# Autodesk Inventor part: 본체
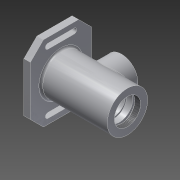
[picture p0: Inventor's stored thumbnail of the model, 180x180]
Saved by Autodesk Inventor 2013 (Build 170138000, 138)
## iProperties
Created: 2017-10
Part Number: 본체
Material: 알루미늄 6061
Document SubType Name: Modeling
Designer: Administrator
Density: 2.71 g/cm^3
Mass: 740.593 g
Surface Area: 658.234 cm^2
Volume: 273.281 cm^3
Author: Administrator
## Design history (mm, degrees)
sketch "스케치1"
  geometry: L1 (44.5, 35)-(57.5, 35); L2 (-57.5, 31)-(44.5, 31); L3 (44.5, 31)-(44.5, 35); L4 (57.5, 35)-(57.5, 0); L5 (57.5, 0)-(-57.5, 0); L6 (-57.5, 0)-(-57.5, 31); 2 further points
  constraints: 12 end point, 3 horizontal, 3 vertical, 2 coincident, 1 midpoint
  dimensions: "d0" = 35 distance from line of point (0, 0) L1; "d1" = 31 distance from line of point (0, 0) L2; "d2" = 115 distance between parallel lines of L6 L4; "d3" = 13 distance between parallel lines of L4 L3
revolve "회전1" sketch "스케치1" stored, may be unused: angle "d4" = 90 deg
sketch "스케치2"
  geometry: L1 (-58, 47)-(58, 47); L2 (58, 47)-(58, -47); L3 (58, -47)-(-58, -47); L4 (-58, -47)-(-58, 47); C1 r 35 at (0, 0) reference; 2 further points
  constraints: 8 end point, 2 midpoint, 2 parallel, 1 horizontal, 1 horizontal alignment, 1 perpendicular, 1 vertical alignment
  dimensions: "d5" = 116 distance of L2.end L3.end; "d7" = 94 distance of L1.end L2.end
extrude "돌출1" join sketch "스케치2" distance "d8" = 10; taper "d9" = 0 deg
chamfer "모따기1" distance "d10" = 20; stored, may be unused: second distance "d11" = 2, angle "d12" = 45 deg
sketch "스케치3"
  geometry: L1 (42, 24)-(50, 24); L2 (50, 24)-(50, -24); L3 (50, -24)-(42, -24); L4 (42, -24)-(42, 24); L5 (-50, -24)-(-42, -24); L6 (-42, -24)-(-42, 24); L7 (-42, 24)-(-50, 24); L8 (-50, 24)-(-50, -24); C1 r 35 at (0, 0) reference
  constraints: 16 end point, 4 parallel, 2 horizontal, 2 perpendicular
  dimensions: "d13" = 48 distance of L1.end L2.end; "d15" = 48 distance of L7.end L5.start; "d16" = 24 distance from line of C1.centre L1; "d17" = 24 distance from line of C1.centre L7; "d18" = 8 distance of L6.end L7.end; "d19" = 8 distance of L1.start L1.end; "d21" = 84 distance between parallel lines of L6 L4; "d22" = 42 distance from line of C1.centre L6
extrude "돌출2" cut sketch "스케치3" distance "d23" = 10; taper "d24" = 0 deg
fillet "모깎기1" dims "d25" = 4
sketch "스케치4"
  geometry: L1 (44.5, -50)-(54.5, -50) reference; L2 (54.5, -50)-(54.5, -58) reference; L3 (54.5, -58)-(44.5, -58) reference; L4 (44.5, -58)-(44.5, -50) reference; L5 (54.5, 50)-(44.5, 50) reference; L6 (44.5, 50)-(44.5, 58) reference; L7 (44.5, 58)-(54.5, 58) reference; L8 (54.5, 58)-(54.5, 50) reference; L9 (-57.5, -31)-(-57.5, 31) reference; L10 (-57.5, 31)-(44.5, 31) reference; L11 (44.5, 31)-(44.5, 42) reference; L12 (44.5, 42)-(54.5, 42) reference; L13 (54.5, 42)-(54.5, 35) reference; L14 (54.5, 35)-(57.5, 35) reference; L15 (57.5, 35)-(57.5, -35) reference; L16 (57.5, -35)-(54.5, -35) reference; L17 (54.5, -35)-(54.5, -42) reference; L18 (54.5, -42)-(44.5, -42) reference; L19 (44.5, -42)-(44.5, -31) reference; L20 (44.5, -31)-(-57.5, -31) reference; L21 (-29.75, 0)-(-57.5, 0); L22 (-57.5, -31)-(-57.5, 31) reference; L23 (-57.5, 21)-(-48.5, 21); L24 (-48.5, 21)-(-48.5, 24); L25 (-48.5, 24)-(-45.5, 24); L26 (-45.5, 24)-(-45.5, 20); L27 (-45.5, 20)-(-36.5, 20); L28 (-36.5, 20)-(-36.5, 17.5); L29 (-36.5, 17.5)-(-31.5, 17.5); L30 (-31.5, 18.5)-(-29.75, 18.5); L31 (-29.75, 18.5)-(-29.75, 0); L32 (-31.5, 17.5)-(-31.5, 18.5); 1 further point
  constraints: 22 end point, 4 horizontal, 4 vertical, 1 midpoint, 1 perpendicular, 1 point on line
  dimensions: "d26" = 21 distance between parallel lines of L21 L23; "d28" = 9 distance of L23.start L23.end; "d29" = 3 distance of L24.end L25.end; "d30" = 24 distance between parallel lines of L21 L25; "d31" = 12 distance between parallel lines of L9 L26; "d32" = 20 distance between parallel lines of L21 L27; "d33" = 21 distance between parallel lines of L9 L28; "d34" = 17.5 distance between parallel lines of L21 L29; "d35" = 5 distance of L28.end L29.end; "d36" = 1.75 distance of L30.start L30.end; "d37" = 18.5 distance between parallel lines of L21 L30
revolve "회전2" sketch "스케치4" stored, may be unused: angle "d38" = 90 deg
sketch "스케치5"
  geometry: C1 r 18.5 at (0, 0) reference; C2 r 17.5 at (0, 0)
  constraints: 1 centre point, 1 coincident
  dimensions: "d39" = 35 diameter of C2
extrude "돌출3" cut sketch "스케치5" distance "d41" = 60; taper "d42" = 0 deg
node "작업 평면1"
sketch "스케치6"
  geometry: C1 r 26 at (0, 0); 1 further point
  constraints: 1 centre point, 1 coincident
  dimensions: "d44" = 52 diameter of C1
extrude "돌출4" cut sketch "스케치6" stored distance "d46" = 38; taper "d47" = 0 deg
fillet "모깎기2" dims "d53" = 3
sketch "스케치8"
  geometry: C1 r 16.5 at (0, 0); C2 r 17.5 at (0, 0) reference; 1 further point
  constraints: 3 coincident, 1 centre point
  dimensions: "d54" = 33 diameter of C1
extrude "돌출5" cut sketch "스케치8" distance "d56" = 5; taper "d57" = 0 deg
fillet "모깎기4" dims "d59" = 3
sketch "스케치9"
  geometry: L1 (44.5, -50)-(54.5, -50) reference; L2 (54.5, -50)-(54.5, -58) reference; L3 (54.5, -58)-(44.5, -58) reference; L4 (44.5, -58)-(44.5, -50) reference; L5 (54.5, 50)-(44.5, 50) reference; L6 (44.5, 50)-(44.5, 58) reference; L7 (44.5, 58)-(54.5, 58) reference; L8 (54.5, 58)-(54.5, 50) reference; L9 (57.5, 35)-(57.5, -35) reference; L10 (57.5, -35)-(54.5, -35) reference; L11 (54.5, -35)-(54.5, -42) reference; L12 (54.5, -42)-(44.5, -42) reference; L13 (44.5, -42)-(44.5, -31) reference; L14 (44.5, -31)-(-57.5, -31) reference; L15 (-57.5, -31)-(-57.5, -21) reference; L16 (-57.5, -21)-(-48.5, -21) reference; L17 (-48.5, -21)-(-48.5, -24) reference; L18 (-48.5, -24)-(-45.5, -24) reference; L19 (-45.5, -24)-(-45.5, -20) reference; L20 (-45.5, -20)-(-36.5, -20) reference; L21 (-36.5, -20)-(-36.5, -17.5) reference; L22 (-36.5, -17.5)-(-31.5, -17.5) reference; L23 (-31.5, -17.5)-(-31.5, -18.5) reference; L24 (-31.5, -18.5)-(-29.75, -18.5) reference; L25 (-20.5, -17.5)-(-20.5, -23) reference; L26 (-17.5, -26)-(14.5, -26) reference; L27 (17.5, -23)-(17.5, -17.5) reference; L28 (30.25, -17.5)-(30.25, -16.5) reference; L29 (30.25, -16.5)-(32.25, -16.5) reference; L30 (35.25, -13.5)-(35.25, 13.5) reference; L31 (32.25, 16.5)-(30.25, 16.5) reference; L32 (30.25, 16.5)-(30.25, 17.5) reference; L33 (17.5, 17.5)-(17.5, 23) reference; L34 (14.5, 26)-(-17.5, 26) reference; L35 (-20.5, 23)-(-20.5, 17.5) reference; L36 (-29.75, 18.5)-(-31.5, 18.5) reference; L37 (-31.5, 18.5)-(-31.5, 17.5) reference; L38 (-31.5, 17.5)-(-36.5, 17.5) reference; L39 (-36.5, 17.5)-(-36.5, 20) reference; L40 (-36.5, 20)-(-45.5, 20) reference; L41 (-45.5, 20)-(-45.5, 24) reference; L42 (-45.5, 24)-(-48.5, 24) reference; L43 (-48.5, 24)-(-48.5, 21) reference; L44 (-48.5, 21)-(-57.5, 21) reference; L45 (-57.5, 21)-(-57.5, 31) reference; L46 (-57.5, 31)-(44.5, 31) reference; L47 (44.5, 31)-(44.5, 42) reference; L48 (44.5, 42)-(54.5, 42) reference; L49 (54.5, 42)-(54.5, 35) reference; L50 (54.5, 35)-(57.5, 35) reference; L51 (35.25, 10)-(37.95, 10); L52 (37.95, 10)-(37.95, 12.2); L53 (38.25, 12.5)-(44.55, 12.5); L54 (45.25, 12.904)-(45.25, 14.129); L55 (44.55, 12.5)-(45.25, 12.904); L56 (57.5, -35)-(57.5, 35) reference; L57 (46.93, 16.823)-(57.5, 22); L58 (57.5, 0)-(35.25, 0); L59 (35.25, -13.5)-(35.25, 13.5) reference; L60 (35.25, 0)-(35.25, 10); L61 (57.5, 0)-(57.5, 22); L62 (-29.75, -18.5)-(-29.75, -17.5) reference; L63 (-29.75, -17.5)-(-20.5, -17.5) reference; L64 (17.5, -17.5)-(30.25, -17.5) reference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; A1 r 3 centre (-17.5, -23) between (-20.5, -23) and (-17.5, -26) reference; A2 r 3 centre (14.5, -23) between (14.5, -26) and (17.5, -23) reference; A3 r 3 centre (32.25, -13.5) between (32.25, -16.5) and (35.25, -13.5) reference; A4 r 3 centre (32.25, 13.5) between (35.25, 13.5) and (32.25, 16.5) reference; A5 r 3 centre (14.5, 23) between (17.5, 23) and (14.5, 26) reference; A6 r 3 centre (-17.5, 23) between (-17.5, 26) and (-20.5, 23) reference; A7 r 0.3 centre (38.25, 12.2) between (38.25, 12.5) and (37.95, 12.2); A8 r 3 centre (48.25, 14.129) between (46.93, 16.823) and (45.25, 14.129); 2 further points
  constraints: 18 end point, 4 point on circle, 4 point on line, 4 tangent, 4 vertical, 2 centre point, 2 midpoint, 1 horizontal, 1 perpendicular
  dimensions: "d60" = 2.7 distance of L51.start L51.end; "d62" = 10 distance from line of point (0, 0) L51; "d63" = 12.5 distance from line of point (0, 0) L53; "d64" = 0.3 radius of A7; "d65" = 7.3 distance between parallel lines of L52 L54; "d68" = 30 deg angle of L53 L55; "d69" = 0.7 horizontal distance of L54.start L53.end; "d72" = 16 vertical distance of point (0, 0) point (45.25, 16); "d73" = 22 vertical distance of point (0, 0) L57.end; "d74" = 3 radius of A8
revolve "회전3" sketch "스케치9" stored, may be unused: angle "d75" = 90 deg
feature "스레드1" dims "d76" = 10, "d77" = 0
sketch "스케치10"
  geometry: L1 (-57.5, -31)-(-57.5, 31) reference; C1 r 25 at (-1.5, 0); 1 further point
  constraints: 1 centre point, 1 horizontal alignment
  dimensions: "d78" = 56 distance from line of L1 C1.centre; "d79" = 50 diameter of C1
extrude "돌출6" join sketch "스케치10" distance "d80" = 47; taper "d81" = 0 deg
sketch "스케치11"
  geometry: C1 r 25 at (0, 0) reference; C2 r 16 at (0, 0); 1 further point
  constraints: 1 centre point, 1 coincident
  dimensions: "d82" = 32 diameter of C2
extrude "돌출7" cut sketch "스케치11" distance "d84" = 47; taper "d85" = 0 deg
chamfer "모따기3" distance "d86" = 1; stored, may be unused: second distance "d87" = 2, angle "d88" = 45 deg
sketch "스케치12"
  geometry: C1 r 25 at (0, 0) reference; 2 further points
  constraints: 1 vertical alignment
  dimensions: "d89" = 20.5 distance of C1.centre point (0, 20.5)
hole "구멍1" sketch "스케치12" at (0, 20.5) diameter "d90" = 2.459; stored, may be unused: countersink angle "d94" = 90 deg, drill point angle "d96" = 118 deg; dims "d91" = 6, "d92" = 4, "d93" = 2, "d95" = 8
node "작업 평면3"
sketch "스케치14"
  geometry: L1 (-56, -31)-(-56, 31) reference; L2 (25, 47)-(-25, 47) reference; 2 further points
  constraints: 1 other
  dimensions: "d101" = 56 distance from line of L1 point (0, 37); "d102" = 10 distance from line of L2 point (0, 37)
feature "엠보싱1" sketch "스케치14" dims "d0" = 35, "d1" = 31, "d2" = 115, "d3" = 13, "d103" = 0.5, "d104" = 0
sketch "스케치15"
  geometry: L1 (26.5, 17.5)-(26.5, 0) reference; L2 (26.5, 0)-(17.5, 0) reference; L3 (17.5, 0)-(17.5, 46) reference; L4 (17.5, 46)-(18.5, 47) reference; L5 (18.5, 47)-(26.5, 47) reference; L6 (26.5, 47)-(26.5, 31) reference; L7 (26.5, 31)-(57.5, 31) reference; L8 (57.5, 31)-(57.5, 21) reference; L9 (57.5, 21)-(48.5, 21) reference; L10 (48.5, 21)-(48.5, 24) reference; L11 (48.5, 24)-(45.5, 24) reference; L12 (45.5, 24)-(45.5, 20) reference; L13 (45.5, 20)-(36.5, 20) reference; L14 (36.5, 20)-(36.5, 17.5) reference; L15 (36.5, 17.5)-(31.5, 17.5) reference; L16 (31.5, 17.5)-(31.5, 18.5) reference; L17 (31.5, 18.5)-(29.75, 18.5) reference; L18 (-54.5, -47)-(-54.5, -35) reference; L19 (-54.5, -35)-(-57.5, -35) reference; L20 (-57.5, -35)-(-57.5, -22) reference; L21 (-57.5, -22)-(-46.93, -16.823) reference; L22 (-45.25, -14.129)-(-45.25, -12.904) reference; L23 (-45.25, -12.904)-(-44.55, -12.5) reference; L24 (-44.55, -12.5)-(-38.25, -12.5) reference; L25 (-37.95, -12.2)-(-37.95, -10) reference; L26 (-37.95, -10)-(-35.25, -10) reference; L27 (-35.25, -10)-(-35.25, -13.5) reference; L28 (-32.25, -16.5)-(-30.25, -16.5) reference; L29 (-30.25, -16.5)-(-30.25, -17.5) reference; L30 (-17.5, -17.5)-(-17.5, -23) reference; L31 (-14.5, -26)-(17.5, -26) reference; L32 (20.5, -23)-(20.5, -17.5) reference; L33 (29.75, -18.5)-(31.5, -18.5) reference; L34 (31.5, -18.5)-(31.5, -17.5) reference; L35 (31.5, -17.5)-(36.5, -17.5) reference; L36 (36.5, -17.5)-(36.5, -20) reference; L37 (36.5, -20)-(45.5, -20) reference; L38 (45.5, -20)-(45.5, -24) reference; L39 (45.5, -24)-(48.5, -24) reference; L40 (48.5, -24)-(48.5, -21) reference; L41 (48.5, -21)-(57.5, -21) reference; L42 (57.5, -21)-(57.5, -31) reference; L43 (57.5, -31)-(-44.5, -31) reference; L44 (-44.5, -31)-(-44.5, -47) reference; L45 (-44.5, -47)-(-54.5, -47) reference; L46 (-54.5, 35)-(-54.5, 47) reference; L47 (-54.5, 47)-(-44.5, 47) reference; L48 (-44.5, 47)-(-44.5, 31) reference; L49 (-44.5, 31)-(-23.5, 31) reference; L50 (-23.5, 31)-(-23.5, 47) reference; L51 (-23.5, 47)-(-15.5, 47) reference; L52 (-15.5, 47)-(-14.5, 46) reference; L53 (-14.5, 46)-(-14.5, 0) reference; L54 (-14.5, 0)-(-23.5, 0) reference; L55 (-23.5, 0)-(-23.5, 17.5) reference; L56 (-30.25, 17.5)-(-30.25, 16.5) reference; L57 (-30.25, 16.5)-(-32.25, 16.5) reference; L58 (-35.25, 13.5)-(-35.25, 10) reference; L59 (-35.25, 10)-(-37.95, 10) reference; L60 (-37.95, 10)-(-37.95, 12.2) reference; L61 (-38.25, 12.5)-(-44.55, 12.5) reference; L62 (-44.55, 12.5)-(-45.25, 12.904) reference; L63 (-45.25, 12.904)-(-45.25, 14.129) reference; L64 (-46.93, 16.823)-(-57.5, 22) reference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; A1 r 3 centre (-48.25, -14.129) between (-46.93, -16.823) and (-45.25, -14.129) reference; A2 r 0.3 centre (-38.25, -12.2) between (-38.25, -12.5) and (-37.95, -12.2) reference; A3 r 3 centre (-32.25, -13.5) between (-35.25, -13.5) and (-32.25, -16.5) reference; A4 r 3 centre (-14.5, -23) between (-17.5, -23) and (-14.5, -26) reference; A5 r 3 centre (17.5, -23) between (17.5, -26) and (20.5, -23) reference; A6 r 3 centre (-32.25, 13.5) between (-32.25, 16.5) and (-35.25, 13.5) reference; A7 r 0.3 centre (-38.25, 12.2) between (-37.95, 12.2) and (-38.25, 12.5) reference; A8 r 3 centre (-48.25, 14.129) between (-45.25, 14.129) and (-46.93, 16.823) reference; A9 r 3 centre (-48.25, -14.129) between (-46.93, -16.823) and (-45.25, -14.129) reference; A10 r 0.3 centre (-38.25, -12.2) between (-38.25, -12.5) and (-37.95, -12.2) reference; A11 r 3 centre (-32.25, -13.5) between (-35.25, -13.5) and (-32.25, -16.5) reference; A12 r 3 centre (-14.5, -23) between (-17.5, -23) and (-14.5, -26) reference; A13 r 3 centre (17.5, -23) between (17.5, -26) and (20.5, -23) reference; A14 r 3 centre (-32.25, 13.5) between (-32.25, 16.5) and (-35.25, 13.5) reference; A15 r 0.3 centre (-38.25, 12.2) between (-37.95, 12.2) and (-38.25, 12.5) reference; A16 r 3 centre (-48.25, 14.129) between (-45.25, 14.129) and (-46.93, 16.823) reference; 2 further points
  constraints: 2 end point, 2 midpoint, 1 horizontal, 1 horizontal alignment, 1 point on line
revolve "회전4" sketch "스케치15" stored, may be unused: angle "d105" = 90 deg
sketch "스케치16"
  geometry: C1 r 21 at (0, 0) reference; C2 r 31 at (0, 0) reference; C3 r 21 at (0, 0)
  constraints: 1 centre point, 1 coincident
  dimensions: "d106" = 42 diameter of C3
extrude "돌출8" join sketch "스케치16" distance "d108" = 9; taper "d109" = 0 deg
hole "구멍2" diameter "d112" = 40.376; stored, may be unused: countersink angle "d116" = 90 deg, drill point angle "d118" = 118 deg; dims "d113" = 9, "d114" = 4, "d115" = 2, "d117" = 9, "d121" = 10, "d122" = 10
chamfer "모따기4" distance "d119" = 1; stored, may be unused: second distance "d120" = 2, angle "d123" = 45 deg
fillet "모깎기5" dims "d124" = 3
fillet "모깎기6" dims "d125" = 3
node "솔리드1"
pattern_circular "원형 패턴1" dims angle "d98" = 360 deg
node "절단 모서리 투영1"
node "절단 모서리 투영2"
node "절단 모서리 투영3"
node "절단 모서리 투영4"
other parameters: "d43" = -56
